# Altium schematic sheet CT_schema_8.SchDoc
size 280 x 153 mm
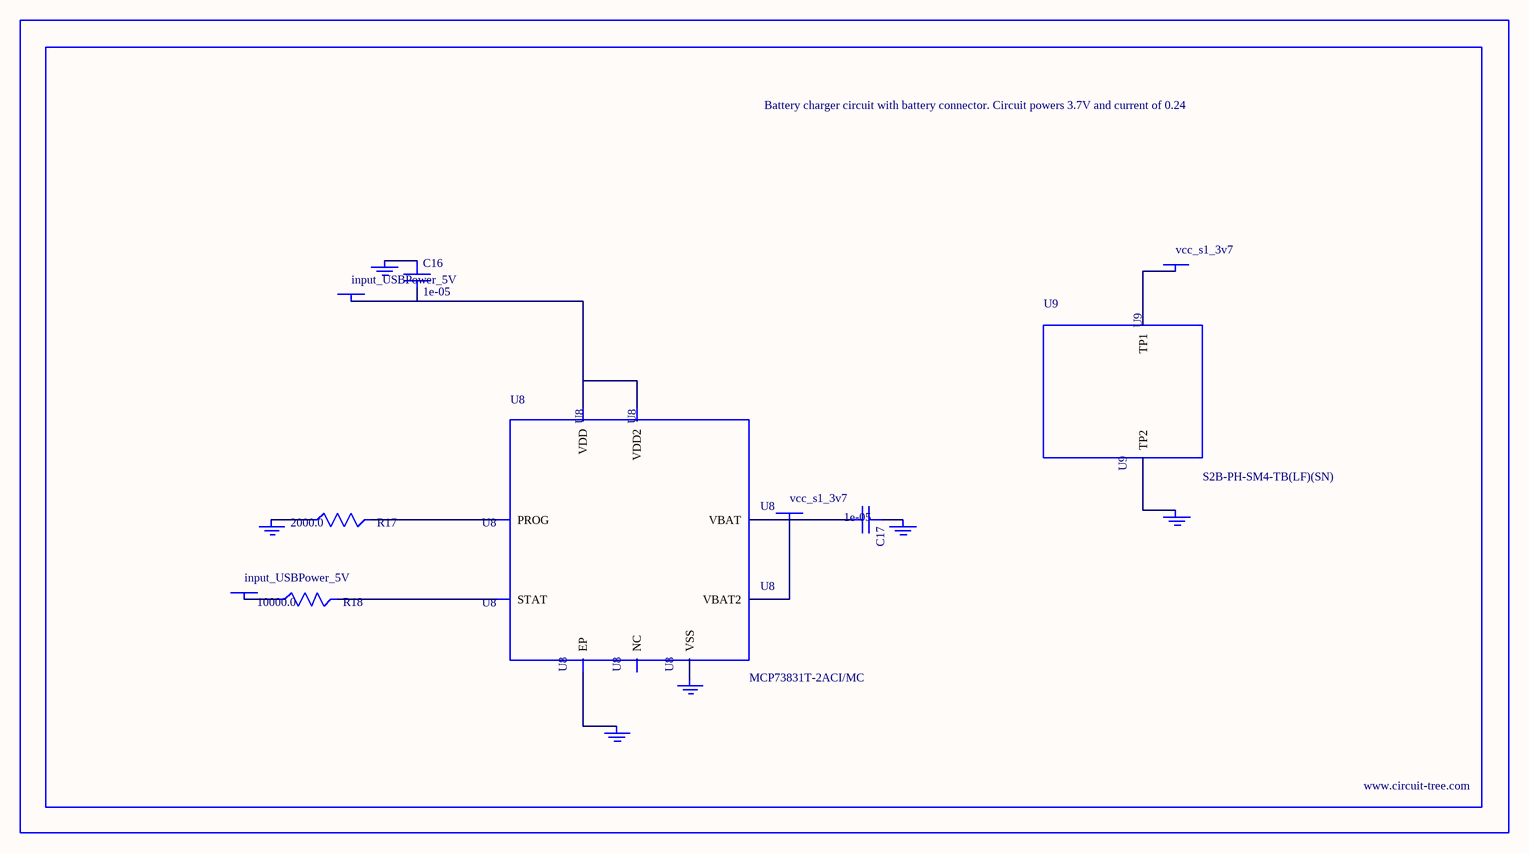
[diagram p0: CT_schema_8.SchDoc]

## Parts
BORDER7  (no value)
C16  1e-05  [C1206]
C17  1e-05  [C1206]
GND_INSTANCE_7_0  (no value)
GND_INSTANCE_7_1  (no value)
GND_INSTANCE_7_2  (no value)
GND_INSTANCE_7_3  (no value)
GND_INSTANCE_7_4  (no value)
GND_INSTANCE_7_5  (no value)
POWER_INSTANCE_7_0  input_USBPower_5V
POWER_INSTANCE_7_1  input_USBPower_5V
POWER_INSTANCE_7_2  vcc_s1_3v7
POWER_INSTANCE_7_3  vcc_s1_3v7
R17  2000.0  [R0603]
R18  10000.0  [R0603]
U8  MCP73831T-2ACI/MC  [DFN8_2X3MC]
U9  S2B-PH-SM4-TB(LF)(SN)  [JST-2-SMD]

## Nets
NetC16_1: C16.1 GND_INSTANCE_7_0.0(GND)
NetC16_2: C16.2 POWER_INSTANCE_7_0.0(PWR) U8.1(VDD) U8.2(VDD2)
NetC17_1: C17.1 GND_INSTANCE_7_1.0(GND)
NetC17_2: C17.2 POWER_INSTANCE_7_2.0(PWR) U8.3(VBAT) U8.4(VBAT2)
NetGND_INSTANCE_7_2_0: GND_INSTANCE_7_2.0(GND) R17.1
NetGND_INSTANCE_7_3_0: GND_INSTANCE_7_3.0(GND) U8.9(EP)
NetGND_INSTANCE_7_4_0: GND_INSTANCE_7_4.0(GND) U8.6(VSS)
NetGND_INSTANCE_7_5_0: GND_INSTANCE_7_5.0(GND) U9.2(TP2)
NetPOWER_INSTANCE_7_1_0: POWER_INSTANCE_7_1.0(PWR) R18.1
NetPOWER_INSTANCE_7_3_0: POWER_INSTANCE_7_3.0(PWR) U9.1(TP1)
NetR17_2: R17.2 U8.8(PROG)
NetR18_2: R18.2 U8.5(STAT)

Not connected (* = marked no-connect by the designer): U8 7(NC)

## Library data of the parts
BORDER7 = BORDER_PAGE7
C16 C17 = C1206C106K3RACTU
GND_INSTANCE_7_0-GND_INSTANCE_7_5 = GND
POWER_INSTANCE_7_0-POWER_INSTANCE_7_3 = PWR
R17 = RC0603JR-072KL
R18 = RC0603JR-0710KL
